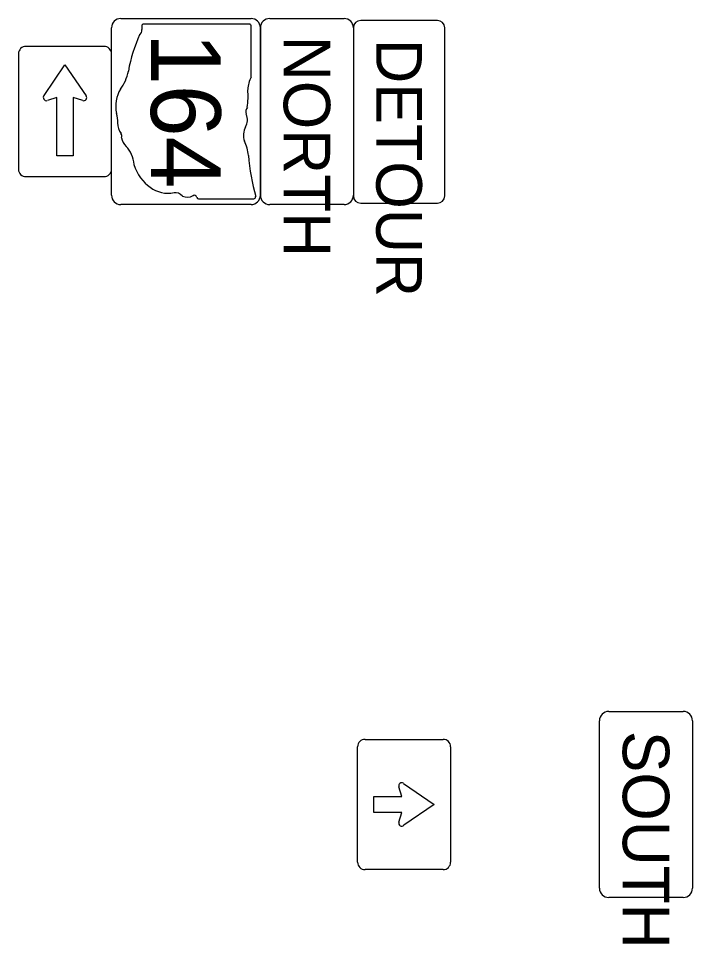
# Model space of a CAD drawing. Extents: x -202 to 1556, y 0 to 676.
# Drawn here: x -5.6 to 85, y 497.2 to 621.5 of the extents above; entities that cross this region are included whole.
import ezdxf

# ---------------------------------------------------------------- set-up
doc = ezdxf.new("R2010")
doc.units = 0
doc.layers.add('GM_X_Minor_Lake', color=7, linetype='Continuous')
doc.layers.add('GM_X_Minor_Lake_Text', color=7, linetype='Continuous')

msp = doc.modelspace()

# ---------------------------------------------------------------- linework, layer by layer
at = {"layer": 'GM_X_Minor_Lake'}
for p, q in [((28.19, 621.51), (38.19, 621.51)), ((25.47, 620.73), (11.24, 620.73)), ((25.72, 613.63), (25.72, 620.5)), ((26.94, 597.76), (26.94, 620.26)), ((39.44, 620.26), (39.44, 597.76)), ((18.62, 597.29), (26.07, 597.29)), ((18.63, 597.29), (18.62, 597.29)), ((38.19, 596.51), (28.19, 596.51)), ((41, 524.65), (51.5, 524.65)), ((40, 508.15), (40, 523.65)), ((52.5, 523.65), (52.5, 508.15)), ((45.94, 516.99), (45.54, 518.28)), ((46.18, 518.74), (50.31, 515.9)), ((42.19, 514.81), (42.19, 516.99)), ((42.19, 516.99), (45.94, 516.99)), ((50.31, 515.9), (46.23, 513.1)), ((45.94, 514.81), (42.19, 514.81)), ((45.54, 513.52), (45.94, 514.81)), ((51.5, 507.15), (41, 507.15))]:
    msp.add_line(p, q, dxfattribs=at)
for points in [[(8.19, 621.51), (25.69, 621.51)], [(6.94, 597.76), (6.94, 620.26)], [(26.94, 620.26), (26.94, 597.76)], [(25.69, 596.51), (8.19, 596.51)]]:
    msp.add_lwpolyline(points, dxfattribs=at)
for centre, radius, start, end in [((8.19, 620.26), 1.25, 90, 180), ((25.69, 620.26), 1.25, 360, 90), ((28.19, 620.26), 1.25, 90, 180), ((38.19, 620.26), 1.25, 360, 90), ((8.19, 597.76), 1.25, 180, 270), ((25.69, 597.76), 1.25, 270, 360), ((28.19, 597.76), 1.25, 180, 270), ((38.19, 597.76), 1.25, 270, 360), ((41, 523.65), 1, 90, 180), ((51.5, 523.65), 1, 0, 90), ((45.94, 518.4), 0.417, 55.4112, 197.2046), ((45.94, 513.4), 0.417, 162.7954, 315.0096), ((41, 508.15), 1, 180, 270), ((51.5, 508.15), 1, 270, 0)]:
    msp.add_arc(centre, radius, start, end, dxfattribs=at)
for centre, major_axis, start_param, end_param in [((11.21, 620.46), (0, -0.274), 3.00124, 4.508301), ((12.67, 620.41), (0, -2.09), 4.665946, 4.897461), ((25.5, 620.46), (0, -0.272), 1.712693, 3.28349), ((23.21, 610.47), (0, -17.95), 4.195997, 4.488961), ((10.42, 619.99), (0, -0.754), 0.519207, 1.627899), ((4.85, 615.82), (0, -5.62), 0.823519, 1.323587), ((27.37, 612), (0, -2.63), 4.042523, 4.731795), ((10.35, 609.75), (0, -3.56), 4.026481, 4.996735), ((17.73, 611.12), (0, -9.45), 1.404758, 1.657858), ((25.58, 608.98), (0, -0.76), 3.836095, 5.185415), ((5.43, 607.69), (0, -2.93), 1.495662, 1.94098), ((23.93, 607.86), (0, -1.58), 0.950623, 2.079405), ((9.28, 607.43), (0, -1.9), 4.691044, 5.507374), ((26.19, 605.82), (0, -1.9), 4.081561, 5.145723), ((7.9, 605.71), (0, -0.535), 1.147584, 2.315152), ((9.86, 605.94), (0, -2.01), 4.937069, 5.64225), ((7.25, 601.62), (0, -3.4), 1.647645, 2.488434), ((21.37, 602.47), (0, -5), 1.699011, 2.107814), ((45.12, 605.64), (0, -24.85), 4.814394, 5.042369), ((14.56, 604.25), (0, -6.22), 5.101752, 6.440018), ((15.51, 596.35), (0, -1.76), 2.387724, 3.262537), ((17.14, 599.92), (0, -2.42), 5.934695, 6.695948), ((18.08, 597.35), (0, -0.404), 1.883978, 3.671073), ((18.6, 597.57), (0, -0.279), 5.05454, 6.418171), ((26.1, 597.55), (0, -0.261), 6.141152, 7.989035)]:
    msp.add_ellipse(centre, major_axis=major_axis, ratio=0.8, start_param=start_param, end_param=end_param, dxfattribs=at)
at = {"layer": 'GM_X_Minor_Lake_Text'}
for p, q in [((5.94, 617.76), (-4.56, 617.76)), ((-5.56, 616.76), (-5.56, 601.26)), ((6.94, 601.26), (6.94, 616.76)), ((-2.1, 611.18), (0.69, 615.26)), ((0.69, 615.26), (3.54, 611.12)), ((-0.4, 610.88), (-1.68, 610.48)), ((-0.4, 603.07), (-0.4, 610.88)), ((1.79, 610.88), (1.79, 603.07)), ((3.07, 610.48), (1.79, 610.88)), ((1.79, 603.07), (-0.4, 603.07)), ((-4.56, 600.26), (5.94, 600.26)), ((73.75, 528.4), (83.75, 528.4)), ((72.5, 504.65), (72.5, 527.15)), ((85, 527.15), (85, 504.65)), ((83.75, 503.4), (73.75, 503.4))]:
    msp.add_line(p, q, dxfattribs=at)
for points in [[(39.44, 620.26), (39.44, 597.67)], [(50.73, 621.24), (40.42, 621.24)], [(51.72, 597.67), (51.72, 620.26)], [(40.42, 596.69), (50.73, 596.69)]]:
    msp.add_lwpolyline(points, dxfattribs=at)
for centre, radius, start, end in [((40.42, 620.26), 0.982, 90, 180), ((50.73, 620.26), 0.982, 360, 90), ((-4.56, 616.76), 1, 90, 180), ((5.94, 616.76), 1, 0, 90), ((-1.81, 610.88), 0.417, 134.9904, 287.2046), ((3.19, 610.88), 0.417, 252.7954, 34.5888), ((-4.56, 601.26), 1, 180, 270), ((5.94, 601.26), 1, 270, 0), ((40.42, 597.67), 0.982, 180, 270), ((50.73, 597.67), 0.982, 270, 360), ((73.75, 527.15), 1.25, 90, 180), ((83.75, 527.15), 1.25, 360, 90), ((73.75, 504.65), 1.25, 180, 270), ((83.75, 504.65), 1.25, 270, 360)]:
    msp.add_arc(centre, radius, start, end, dxfattribs=at)

# ---------------------------------------------------------------- texts
at = {"layer": 'GM_X_Minor_Lake'}
for s, height, p in [('164', 9.375, (12.24, 619.58)), ('NORTH', 6.25, (30.07, 619.17))]:
    msp.add_text(s, height=height, rotation=270, dxfattribs=at).set_placement(p)
at = {"layer": 'GM_X_Minor_Lake_Text'}
for s, height, p in [('DETOUR', 6.138, (42.51, 618.74)), ('SOUTH', 6.25, (75.63, 525.79))]:
    msp.add_text(s, height=height, rotation=270, dxfattribs=at).set_placement(p)

doc.saveas('drawing.dxf')
